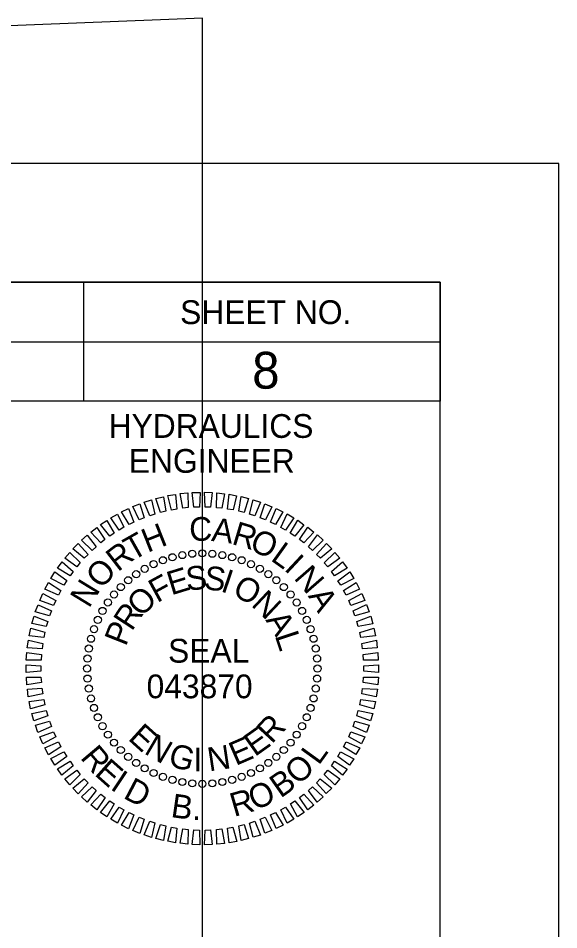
# Model space of a CAD drawing. Extents: x 1637092 to 1638792, y 884647 to 885778.
# Drawn here: x 1638677.9 to 1638791.7, y 885585.9 to 885777.7 of the extents above; entities that cross this region are included whole.
import ezdxf

# ---------------------------------------------------------------- set-up
doc = ezdxf.new("R2010")
doc.units = 0
for name, color, linetype in [('Scratch_Level_3', 7, 'Continuous'), ('Sheet Cutting Line CELL', 7, 'Continuous'), ('Sheet Data Field CELL', 7, 'Continuous'), ('Sheet PE Seal Cell', 7, 'Continuous'), ('Sheet Plan And Profile CELL', 7, 'Continuous'), ('Sheet Profile CELL', 7, 'Continuous'), ('Stewart Plot Border Xerox6279 and LJ5000', 7, 'Continuous')]:
    doc.layers.add(name, color=color, linetype=linetype)

msp = doc.modelspace()

# ---------------------------------------------------------------- linework, layer by layer
at = {"layer": 'Scratch_Level_3'}
msp.add_lwpolyline([(1637316.66, 885722.14), (1637316.66, 884697.14), (1638716.66, 884697.14), (1638716.66, 885777.71)], close=True, dxfattribs=at)
at = {"layer": 'Sheet Cutting Line CELL'}
msp.add_line((1638783.66, 885747.14), (1637099.66, 885747.14), dxfattribs=at)
at = {"layer": 'Sheet PE Seal Cell'}
msp.add_line((1638716.63, 885640.84), (1638716.63, 885640.84), dxfattribs=at)
for points in [[(1638707.86, 885673.68), (1638706.87, 885676.64), (1638708.45, 885677), (1638708.96, 885673.96)], [(1638710.17, 885674.21), (1638709.39, 885677.23), (1638710.99, 885677.49), (1638711.29, 885674.42)], [(1638712.51, 885674.58), (1638711.95, 885677.65), (1638713.56, 885677.79), (1638713.65, 885674.71)], [(1638714.88, 885674.79), (1638714.53, 885677.89), (1638716.15, 885677.91), (1638716.02, 885674.83)], [(1638717.25, 885674.83), (1638717.12, 885677.94), (1638718.73, 885677.86), (1638718.39, 885674.79)], [(1638719.62, 885674.7), (1638719.71, 885677.82), (1638721.31, 885677.62), (1638720.75, 885674.59)], [(1638721.97, 885674.41), (1638722.28, 885677.51), (1638723.86, 885677.21), (1638723.1, 885674.22)], [(1638724.3, 885673.95), (1638724.82, 885677.03), (1638726.38, 885676.61), (1638725.41, 885673.69)], [(1638703.37, 885672.14), (1638701.99, 885674.93), (1638703.49, 885675.51), (1638704.43, 885672.57)], [(1638705.59, 885672.99), (1638704.4, 885675.87), (1638705.95, 885676.34), (1638706.67, 885673.35)], [(1638726.59, 885673.34), (1638727.33, 885676.37), (1638728.86, 885675.84), (1638727.68, 885672.99)], [(1638728.83, 885672.57), (1638729.78, 885675.54), (1638731.27, 885674.91), (1638729.9, 885672.14)], [(1638699.14, 885669.99), (1638697.38, 885672.56), (1638698.8, 885673.35), (1638700.13, 885670.57)], [(1638701.22, 885671.14), (1638699.64, 885673.83), (1638701.11, 885674.51), (1638702.24, 885671.64)], [(1638731.02, 885671.64), (1638732.17, 885674.54), (1638733.61, 885673.8), (1638732.05, 885671.14)], [(1638733.13, 885670.56), (1638734.48, 885673.37), (1638735.87, 885672.54), (1638734.12, 885669.99)], [(1638697.15, 885668.7), (1638695.22, 885671.14), (1638696.57, 885672.02), (1638698.1, 885669.34)], [(1638735.16, 885669.33), (1638736.71, 885672.05), (1638738.03, 885671.12), (1638736.11, 885668.7)], [(1638693.47, 885665.72), (1638691.21, 885667.87), (1638692.43, 885668.93), (1638694.31, 885666.49)], [(1638695.26, 885667.27), (1638693.16, 885669.58), (1638694.45, 885670.55), (1638696.15, 885667.98)], [(1638737.11, 885667.97), (1638738.83, 885670.57), (1638740.09, 885669.55), (1638738.01, 885667.28)], [(1638738.95, 885666.48), (1638740.85, 885668.95), (1638742.04, 885667.85), (1638739.8, 885665.72)], [(1638691.79, 885664.04), (1638689.38, 885666.03), (1638690.53, 885667.17), (1638692.58, 885664.87)], [(1638740.68, 885664.86), (1638742.76, 885667.19), (1638743.86, 885666.01), (1638741.48, 885664.04)], [(1638690.23, 885662.25), (1638687.69, 885664.07), (1638688.75, 885665.29), (1638690.96, 885663.13)], [(1638742.3, 885663.12), (1638744.53, 885665.3), (1638745.55, 885664.05), (1638743.04, 885662.25)], [(1638688.8, 885660.36), (1638686.14, 885661.99), (1638687.12, 885663.28), (1638689.47, 885661.28)], [(1638743.79, 885661.28), (1638746.17, 885663.3), (1638747.1, 885661.97), (1638744.47, 885660.36)], [(1638687.51, 885658.37), (1638684.74, 885659.82), (1638685.62, 885661.17), (1638688.11, 885659.34)], [(1638745.15, 885659.33), (1638747.66, 885661.18), (1638748.5, 885659.8), (1638745.76, 885658.37)], [(1638686.36, 885656.29), (1638683.5, 885657.54), (1638684.28, 885658.96), (1638686.89, 885657.3)], [(1638746.37, 885657.3), (1638749.01, 885658.97), (1638749.74, 885657.53), (1638746.91, 885656.29)], [(1638685.35, 885654.14), (1638682.41, 885655.19), (1638683.1, 885656.66), (1638685.81, 885655.19)], [(1638747.45, 885655.18), (1638750.19, 885656.67), (1638750.82, 885655.18), (1638747.92, 885654.14)], [(1638684.5, 885651.93), (1638681.49, 885652.77), (1638682.07, 885654.28), (1638684.88, 885653)], [(1638748.37, 885653), (1638751.22, 885654.29), (1638751.74, 885652.76), (1638748.77, 885651.93)], [(1638683.8, 885649.66), (1638680.75, 885650.29), (1638681.22, 885651.84), (1638684.11, 885650.76)], [(1638749.14, 885650.76), (1638752.07, 885651.84), (1638752.49, 885650.28), (1638749.47, 885649.66)], [(1638683.27, 885647.35), (1638680.18, 885647.76), (1638680.54, 885649.34), (1638683.5, 885648.47)], [(1638749.76, 885648.46), (1638752.75, 885649.34), (1638753.06, 885647.76), (1638750, 885647.35)], [(1638682.9, 885645.01), (1638679.78, 885645.2), (1638680.04, 885646.8), (1638683.05, 885646.14)], [(1638750.21, 885646.13), (1638753.26, 885646.8), (1638753.45, 885645.2), (1638750.37, 885645)], [(1638682.69, 885642.64), (1638679.57, 885642.62), (1638679.71, 885644.23), (1638682.76, 885643.78)], [(1638750.49, 885643.78), (1638753.58, 885644.23), (1638753.67, 885642.62), (1638750.58, 885642.64)], [(1638682.64, 885640.27), (1638679.53, 885640.03), (1638679.56, 885641.65), (1638682.64, 885641.41)], [(1638750.62, 885641.41), (1638753.73, 885641.65), (1638753.7, 885640.03), (1638750.62, 885640.27)], [(1638682.77, 885637.9), (1638679.68, 885637.45), (1638679.6, 885639.06), (1638682.68, 885639.04)], [(1638750.57, 885639.04), (1638753.69, 885639.06), (1638753.55, 885637.45), (1638750.5, 885637.9)], [(1638683.05, 885635.55), (1638680.01, 885634.88), (1638679.81, 885636.48), (1638682.89, 885636.68)], [(1638750.37, 885636.67), (1638753.48, 885636.48), (1638753.23, 885634.88), (1638750.21, 885635.54)], [(1638683.51, 885633.22), (1638680.51, 885632.34), (1638680.2, 885633.92), (1638683.26, 885634.33)], [(1638749.99, 885634.33), (1638753.09, 885633.92), (1638752.72, 885632.34), (1638749.76, 885633.21)], [(1638684.12, 885630.92), (1638681.19, 885629.84), (1638680.77, 885631.4), (1638683.8, 885632.02)], [(1638749.46, 885632.02), (1638752.51, 885631.39), (1638752.04, 885629.85), (1638749.15, 885630.92)], [(1638684.89, 885628.68), (1638682.05, 885627.39), (1638681.52, 885628.92), (1638684.49, 885629.75)], [(1638748.76, 885629.75), (1638751.77, 885628.91), (1638751.19, 885627.4), (1638748.38, 885628.68)], [(1638685.81, 885626.5), (1638683.07, 885625.01), (1638682.44, 885626.5), (1638685.34, 885627.54)], [(1638747.91, 885627.54), (1638750.85, 885626.49), (1638750.17, 885625.02), (1638747.45, 885626.49)], [(1638686.89, 885624.38), (1638684.25, 885622.71), (1638683.52, 885624.15), (1638686.35, 885625.39)], [(1638746.91, 885625.39), (1638749.76, 885624.14), (1638748.98, 885622.72), (1638746.38, 885624.38)], [(1638688.11, 885622.35), (1638685.6, 885620.5), (1638684.77, 885621.88), (1638687.5, 885623.31)], [(1638745.75, 885623.31), (1638748.52, 885621.87), (1638747.64, 885620.51), (1638745.16, 885622.34)], [(1638689.47, 885620.4), (1638687.09, 885618.38), (1638686.17, 885619.71), (1638688.79, 885621.32)], [(1638744.46, 885621.33), (1638747.12, 885619.69), (1638746.14, 885618.4), (1638743.8, 885620.4)], [(1638690.96, 885618.56), (1638688.73, 885616.38), (1638687.71, 885617.63), (1638690.22, 885619.43)], [(1638743.03, 885619.43), (1638745.57, 885617.61), (1638744.51, 885616.39), (1638742.3, 885618.55)], [(1638692.58, 885616.82), (1638690.51, 885614.49), (1638689.4, 885615.67), (1638691.78, 885617.64)], [(1638741.47, 885617.64), (1638743.88, 885615.65), (1638742.73, 885614.51), (1638740.69, 885616.81)], [(1638694.31, 885615.2), (1638692.41, 885612.73), (1638691.23, 885613.83), (1638693.46, 885615.96)], [(1638739.8, 885615.97), (1638742.05, 885613.81), (1638740.83, 885612.75), (1638738.95, 885615.2)], [(1638696.16, 885613.71), (1638694.43, 885611.11), (1638693.17, 885612.13), (1638695.25, 885614.41)], [(1638738, 885614.41), (1638740.11, 885612.1), (1638738.81, 885611.13), (1638737.11, 885613.7)], [(1638698.1, 885612.35), (1638696.55, 885609.63), (1638695.23, 885610.56), (1638697.15, 885612.98)], [(1638700.13, 885611.12), (1638698.78, 885608.31), (1638697.4, 885609.14), (1638699.14, 885611.69)], [(1638734.12, 885611.69), (1638735.88, 885609.12), (1638734.46, 885608.33), (1638733.13, 885611.12)], [(1638736.11, 885612.98), (1638738.04, 885610.54), (1638736.69, 885609.66), (1638735.17, 885612.34)], [(1638702.24, 885610.04), (1638701.09, 885607.14), (1638699.65, 885607.88), (1638701.21, 885610.54)], [(1638704.43, 885609.12), (1638703.48, 885606.14), (1638701.99, 885606.77), (1638703.37, 885609.54)], [(1638729.89, 885609.54), (1638731.28, 885606.75), (1638729.77, 885606.17), (1638728.83, 885609.11)], [(1638732.04, 885610.54), (1638733.62, 885607.85), (1638732.15, 885607.17), (1638731.02, 885610.04)], [(1638706.67, 885608.34), (1638705.93, 885605.31), (1638704.41, 885605.84), (1638705.58, 885608.69)], [(1638708.96, 885607.73), (1638708.44, 885604.65), (1638706.88, 885605.07), (1638707.85, 885608)], [(1638725.41, 885608), (1638726.39, 885605.04), (1638724.81, 885604.68), (1638724.3, 885607.72)], [(1638727.68, 885608.69), (1638728.86, 885605.81), (1638727.32, 885605.34), (1638726.59, 885608.33)], [(1638711.29, 885607.27), (1638710.98, 885604.17), (1638709.4, 885604.48), (1638710.16, 885607.46)], [(1638713.65, 885606.98), (1638713.56, 885603.86), (1638711.95, 885604.06), (1638712.51, 885607.09)], [(1638716.01, 885606.86), (1638716.14, 885603.74), (1638714.53, 885603.82), (1638714.87, 885606.89)], [(1638718.39, 885606.9), (1638718.73, 885603.79), (1638717.12, 885603.77), (1638717.25, 885606.85)], [(1638720.75, 885607.1), (1638721.31, 885604.03), (1638719.7, 885603.89), (1638719.61, 885606.97)], [(1638723.09, 885607.47), (1638723.87, 885604.45), (1638722.27, 885604.19), (1638721.97, 885607.26)]]:
    msp.add_lwpolyline(points, close=True, dxfattribs=at)
for centre in [(1638712.42, 885664.72), (1638714.52, 885665), (1638716.63, 885665.09), (1638718.74, 885665), (1638720.84, 885664.72), (1638706.38, 885662.82), (1638708.34, 885663.63), (1638710.35, 885664.26), (1638722.91, 885664.26), (1638724.92, 885663.63), (1638726.88, 885662.82), (1638702.72, 885660.7), (1638704.51, 885661.84), (1638728.76, 885661.84), (1638730.54, 885660.7), (1638701.04, 885659.42), (1638732.22, 885659.42), (1638699.48, 885657.99), (1638733.78, 885657.99), (1638696.77, 885654.75), (1638698.05, 885656.43), (1638735.21, 885656.43), (1638736.5, 885654.75), (1638695.63, 885652.97), (1638737.63, 885652.97), (1638694.65, 885651.09), (1638738.61, 885651.09), (1638693.84, 885649.13), (1638739.42, 885649.13), (1638693.21, 885647.12), (1638740.05, 885647.12), (1638692.75, 885645.05), (1638740.51, 885645.05), (1638692.47, 885642.95), (1638740.79, 885642.95), (1638692.38, 885640.84), (1638740.88, 885640.84), (1638692.47, 885638.73), (1638740.79, 885638.73), (1638692.75, 885636.63), (1638740.51, 885636.63), (1638693.21, 885634.56), (1638740.05, 885634.56), (1638693.84, 885632.55), (1638739.42, 885632.55), (1638694.65, 885630.59), (1638738.61, 885630.59), (1638695.63, 885628.72), (1638737.63, 885628.72), (1638696.77, 885626.93), (1638736.5, 885626.93), (1638698.05, 885625.25), (1638735.21, 885625.25), (1638699.48, 885623.69), (1638701.04, 885622.26), (1638732.22, 885622.26), (1638733.78, 885623.69), (1638702.72, 885620.98), (1638730.54, 885620.98), (1638704.51, 885619.84), (1638706.38, 885618.86), (1638726.88, 885618.86), (1638728.76, 885619.84), (1638708.34, 885618.05), (1638710.35, 885617.42), (1638712.42, 885616.96), (1638714.52, 885616.68), (1638716.63, 885616.59), (1638718.74, 885616.68), (1638720.84, 885616.96), (1638722.91, 885617.42), (1638724.92, 885618.05)]:
    msp.add_circle(centre, 0.75, dxfattribs=at)
at = {"layer": 'Sheet Plan And Profile CELL'}
for p, q in [((1638691.66, 885722.09), (1638691.66, 885697.09)), ((1638566.61, 885709.59), (1638766.66, 885709.59))]:
    msp.add_line(p, q, dxfattribs=at)
for points in [[(1638766.66, 885722.14), (1637266.66, 885722.14), (1637266.66, 884672.14), (1638766.66, 884672.14)], [(1638566.61, 885722.14), (1638766.66, 885722.14), (1638766.66, 885697.09), (1638566.61, 885697.09)]]:
    msp.add_lwpolyline(points, close=True, dxfattribs=at)
at = {"layer": 'Sheet Profile CELL'}
for p, q in [((1638691.66, 885722.09), (1638691.66, 885697.09)), ((1638566.61, 885709.59), (1638766.66, 885709.59))]:
    msp.add_line(p, q, dxfattribs=at)
for points in [[(1638766.66, 885722.14), (1637266.66, 885722.14), (1637266.66, 884672.14), (1638766.66, 884672.14)], [(1638566.61, 885722.14), (1638766.66, 885722.14), (1638766.66, 885697.09), (1638566.61, 885697.09)]]:
    msp.add_lwpolyline(points, close=True, dxfattribs=at)
at = {"layer": 'Stewart Plot Border Xerox6279 and LJ5000'}
msp.add_lwpolyline([(1637091.66, 884647.14), (1638791.66, 884647.14), (1638791.66, 885747.14), (1637091.66, 885747.14)], close=True, dxfattribs=at)

# ---------------------------------------------------------------- texts
at = {"layer": 'Sheet Data Field CELL'}
msp.add_text('8', height=7.75, dxfattribs=at).set_placement((1638727.13, 885699.75))
at = {"layer": 'Sheet PE Seal Cell'}
for s, rotation, p in [('C', 1.9618, (1638713.96, 885667.64)), ('H', 21.601, (1638705.11, 885665.18)), ('A', 352.4568, (1638718.42, 885667.71)), ('R', 343.4093, (1638722.63, 885667.1)), ('T', 29.3903, (1638701.92, 885663.4)), ('O', 335.2006, (1638726.31, 885665.97)), ('R', 37.5989, (1638698.85, 885661.07)), ('L', 324.4755, (1638730.82, 885663.73)), ('O', 48.3241, (1638695.39, 885657.4)), ('I', 317.0103, (1638733.68, 885661.69)), ('E', 16.986, (1638710.1, 885656.23)), ('S', 5.2237, (1638713.37, 885657.24)), ('S', 353.2648, (1638716.84, 885657.56)), ('I', 341.3058, (1638720.3, 885657.15)), ('N', 311.0704, (1638735.74, 885659.82)), ('N', 58.5345, (1638692.79, 885653.38)), ('F', 28.6639, (1638707.12, 885654.59)), ('O', 332.5504, (1638722.74, 885656.4)), ('O', 44.4727, (1638703.74, 885651.48)), ('N', 316.7416, (1638726.75, 885654.15)), ('A', 300.8599, (1638738.8, 885656.13)), ('R', 56.5721, (1638701.79, 885648.54)), ('A', 301.6915, (1638729.86, 885651.06)), ('P', 68.3344, (1638700.53, 885645.35)), ('L', 288.3556, (1638731.86, 885647.74)), ('R', 47.043, (1638731.26, 885624.82)), ('E', 317.8506, (1638700.82, 885625.98)), ('N', 329.6129, (1638704.18, 885623.07)), ('E', 35.2807, (1638727.69, 885622.18)), ('R', 310.1625, (1638690.8, 885622.03)), ('G', 344.6629, (1638709.22, 885620.45)), ('E', 23.5185, (1638723.66, 885620.31)), ('I', 359.713, (1638714.77, 885619.22)), ('N', 8.4684, (1638718.08, 885619.19)), ('L', 54.176, (1638741.14, 885620.33)), ('E', 318.3712, (1638693.75, 885618.53)), ('O', 43.4508, (1638736.89, 885616.13)), ('I', 326.3511, (1638697.07, 885615.57)), ('B', 35.1087, (1638733.1, 885613.45)), ('D', 332.291, (1638699.79, 885613.68)), ('R', 16.1749, (1638723.32, 885609.59)), ('O', 24.3836, (1638727.71, 885610.87)), ('B', 351.8635, (1638709.86, 885609.61)), ('.', 0.2056, (1638714.46, 885608.96))]:
    msp.add_text(s, height=5, rotation=rotation, dxfattribs=at).set_placement(p)
for s, p in [('SEAL', (1638709.43, 885642.09)), ('043870', (1638704.91, 885634.59))]:
    msp.add_text(s, height=5, dxfattribs=at).set_placement(p)
at = {"layer": 'Sheet Plan And Profile CELL'}
msp.add_text('SHEET NO.', height=5, rotation=360, dxfattribs=at).set_placement((1638711.96, 885713.34))
at = {"layer": 'Sheet Profile CELL'}
for s, p in [('SHEET NO.', (1638711.97, 885713.35)), ('HYDRAULICS', (1638696.92, 885689.39)), ('ENGINEER', (1638701.17, 885682.04))]:
    msp.add_text(s, height=5, dxfattribs=at).set_placement(p)

doc.saveas('drawing.dxf')
